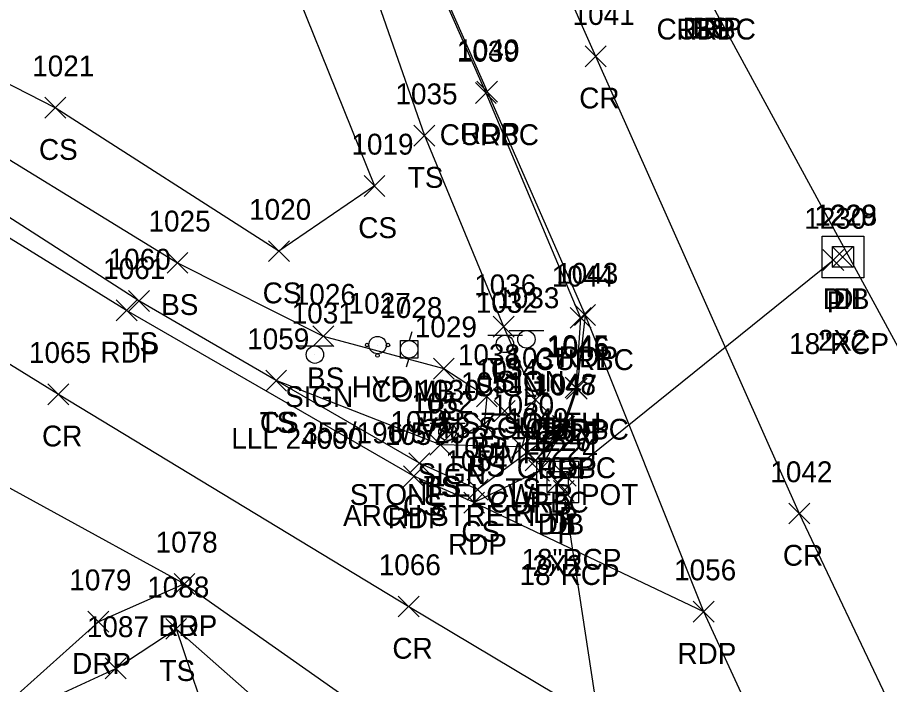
# Model space of a CAD drawing. Extents: x 1504228 to 1506103, y 437717 to 440106.
# Drawn here: x 1505043.8 to 1505127.3, y 438378 to 438441.9 of the extents above; entities that cross this region are included whole.
import ezdxf

# ---------------------------------------------------------------- set-up
doc = ezdxf.new("R2010")
doc.units = 0
for name, color, linetype in [('D_A', 7, 'Continuous'), ('D_C', 7, 'Continuous'), ('D_I', 7, 'Continuous'), ('D_TIC', 7, 'Continuous'), ('DCP', 7, 'Continuous'), ('DS', 7, 'Continuous'), ('L_A', 7, 'Continuous'), ('L_C', 7, 'Continuous'), ('L_I', 7, 'Continuous'), ('L_TIC', 7, 'Continuous'), ('LELB', 7, 'Continuous'), ('P_A', 7, 'Continuous'), ('P_I', 7, 'Continuous'), ('P_TIC', 7, 'Continuous'), ('PET', 7, 'Continuous'), ('PRC', 7, 'Continuous'), ('R_A', 7, 'Continuous'), ('R_I', 7, 'Continuous'), ('R_TIC', 7, 'Continuous'), ('RC', 7, 'Continuous'), ('RDP', 7, 'Continuous'), ('S_A', 7, 'Continuous'), ('S_C', 7, 'Continuous'), ('S_I', 7, 'Continuous'), ('SSGN', 7, 'Continuous'), ('U_A', 7, 'Continuous'), ('U_C', 7, 'Continuous'), ('U_I', 7, 'Continuous'), ('UP', 7, 'Continuous'), ('UWFH', 7, 'Continuous')]:
    doc.layers.add(name, color=color, linetype=linetype)

msp = doc.modelspace()

# ---------------------------------------------------------------- linework, layer by layer
at = {"layer": 'D_TIC'}
for points in [[(1505120.954, 438417.648), (1505122.954, 438419.648)], [(1505122.954, 438417.648), (1505120.954, 438419.648)], [(1505121.856, 438417.952), (1505123.856, 438419.952)], [(1505123.856, 438417.952), (1505121.856, 438419.952)], [(1505094.543, 438396.356), (1505096.543, 438398.356)], [(1505096.543, 438396.356), (1505094.543, 438398.356)], [(1505095.319, 438396.985), (1505097.319, 438398.985)], [(1505097.319, 438396.985), (1505095.319, 438398.985)], [(1505095.144, 438395.524), (1505097.144, 438397.524)], [(1505097.144, 438395.524), (1505095.144, 438397.524)]]:
    msp.add_lwpolyline(points, dxfattribs=at)
at = {"layer": 'DCP'}
for points in [[(1505096.319, 438397.985), (1505121.954, 438418.648)], [(1505105.611, 438334.574), (1505096.144, 438396.524)]]:
    msp.add_lwpolyline(points, dxfattribs=at)
at = {"layer": 'DS'}
for p, q in [((1505120.896, 438420.956), (1505124.896, 438420.956)), ((1505120.896, 438416.956), (1505120.896, 438420.956)), ((1505124.896, 438420.956), (1505124.896, 438416.956)), ((1505121.896, 438417.956), (1505121.896, 438419.956)), ((1505121.896, 438419.956), (1505123.896, 438419.956)), ((1505123.896, 438419.956), (1505123.896, 438417.956)), ((1505122.901, 438418.958), (1505122.901, 438418.958)), ((1505122.901, 438418.958), (1505122.901, 438418.958)), ((1505123.896, 438417.956), (1505121.896, 438417.956)), ((1505124.896, 438416.956), (1505120.896, 438416.956)), ((1505093.564, 438399.391), (1505097.564, 438399.391)), ((1505093.564, 438395.391), (1505093.564, 438399.391)), ((1505097.564, 438399.391), (1505097.564, 438395.391)), ((1505094.564, 438396.391), (1505094.564, 438398.391)), ((1505094.564, 438398.391), (1505096.564, 438398.391)), ((1505096.564, 438398.391), (1505096.564, 438396.391)), ((1505095.569, 438397.393), (1505095.569, 438397.393)), ((1505095.569, 438397.393), (1505095.569, 438397.393)), ((1505096.564, 438396.391), (1505094.564, 438396.391)), ((1505097.564, 438395.391), (1505093.564, 438395.391))]:
    msp.add_line(p, q, dxfattribs=at)
at = {"layer": 'L_TIC'}
for points in [[(1505046.428, 438432.247), (1505048.428, 438434.247)], [(1505048.428, 438432.247), (1505046.428, 438434.247)], [(1505081.791, 438429.573), (1505083.791, 438431.573)], [(1505083.791, 438429.573), (1505081.791, 438431.573)], [(1505077.011, 438424.753), (1505079.011, 438426.753)], [(1505079.011, 438424.753), (1505077.011, 438426.753)], [(1505067.86, 438418.506), (1505069.86, 438420.506)], [(1505069.86, 438418.506), (1505067.86, 438420.506)], [(1505058.135, 438417.385), (1505060.135, 438419.385)], [(1505060.135, 438417.385), (1505058.135, 438419.385)], [(1505054.447, 438413.732), (1505056.447, 438415.732)], [(1505056.447, 438413.732), (1505054.447, 438415.732)], [(1505089.382, 438411.272), (1505091.382, 438413.272)], [(1505091.382, 438411.272), (1505089.382, 438413.272)], [(1505072.108, 438410.364), (1505074.108, 438412.364)], [(1505074.108, 438410.364), (1505072.108, 438412.364)], [(1505083.652, 438407.249), (1505085.652, 438409.249)], [(1505085.652, 438407.249), (1505083.652, 438409.249)], [(1505067.594, 438406.103), (1505069.594, 438408.103)], [(1505069.594, 438406.103), (1505067.594, 438408.103)], [(1505067.594, 438406.103), (1505069.594, 438408.103)], [(1505069.594, 438406.103), (1505067.594, 438408.103)], [(1505087.769, 438404.579), (1505089.769, 438406.579)], [(1505089.769, 438404.579), (1505087.769, 438406.579)], [(1505092.426, 438404.26), (1505094.426, 438406.26)], [(1505094.426, 438404.26), (1505092.426, 438406.26)], [(1505089.481, 438403.182), (1505091.481, 438405.182)], [(1505091.481, 438403.182), (1505089.481, 438405.182)], [(1505087.501, 438401.901), (1505089.501, 438403.901)], [(1505089.501, 438401.901), (1505087.501, 438403.901)], [(1505095.052, 438401.754), (1505097.052, 438403.754)], [(1505097.052, 438401.754), (1505095.052, 438403.754)], [(1505083.317, 438399.963), (1505085.317, 438401.963)], [(1505085.317, 438399.963), (1505083.317, 438401.963)], [(1505083.317, 438399.963), (1505085.317, 438401.963)], [(1505085.317, 438399.963), (1505083.317, 438401.963)], [(1505091.124, 438399.75), (1505093.124, 438401.75)], [(1505093.124, 438399.75), (1505091.124, 438401.75)], [(1505081.309, 438398.178), (1505083.309, 438400.178)], [(1505083.309, 438398.178), (1505081.309, 438400.178)], [(1505086.891, 438395.657), (1505088.891, 438397.657)], [(1505088.891, 438395.657), (1505086.891, 438397.657)], [(1505058.009, 438382.324), (1505060.009, 438384.324)], [(1505060.009, 438382.324), (1505058.009, 438384.324)], [(1505058.009, 438382.324), (1505060.009, 438384.324)], [(1505060.009, 438382.324), (1505058.009, 438384.324)], [(1505052.227, 438378.528), (1505054.227, 438380.528)], [(1505054.227, 438378.528), (1505052.227, 438380.528)]]:
    msp.add_lwpolyline(points, dxfattribs=at)
at = {"layer": 'LELB'}
for points in [[(1505066.129, 438478.342), (1505082.791, 438430.573), (1505090.382, 438412.272), (1505093.426, 438405.26), (1505092.124, 438400.75), (1505084.317, 438400.963), (1505068.594, 438407.103), (1505055.447, 438414.732), (1505017.226, 438439.337)], [(1505057.76, 438475.633), (1505067.049, 438452.95), (1505078.011, 438425.753), (1505068.86, 438419.506), (1505047.428, 438433.247), (1505026.834, 438443.799), (1505009.486, 438446.928)], [(1505009.486, 438446.928), (1505034.88, 438433.257), (1505059.135, 438418.385), (1505073.108, 438411.364), (1505084.652, 438408.249), (1505088.769, 438405.579), (1505088.501, 438402.901), (1505084.317, 438400.963)], [(1505096.052, 438402.754), (1505087.891, 438396.657), (1505082.309, 438399.178), (1505068.594, 438407.103)], [(1505039.492, 438373.185), (1505053.227, 438379.528), (1505059.009, 438383.324), (1505062.619, 438372.642), (1505066.294, 438362.487)], [(1505059.009, 438383.324), (1505071.79, 438372.048), (1505087.996, 438363.895), (1505093.24, 438355.147)]]:
    msp.add_lwpolyline(points, dxfattribs=at)
at = {"layer": 'P_TIC'}
for points in [[(1505098.188, 438437.177), (1505100.188, 438439.177)], [(1505100.188, 438437.177), (1505098.188, 438439.177)], [(1505087.799, 438433.786), (1505089.799, 438435.786)], [(1505089.799, 438433.786), (1505087.799, 438435.786)], [(1505053.269, 438412.829), (1505055.269, 438414.829)], [(1505055.269, 438412.829), (1505053.269, 438414.829)], [(1505097.18, 438412.38), (1505099.18, 438414.38)], [(1505099.18, 438412.38), (1505097.18, 438414.38)], [(1505097.18, 438412.38), (1505099.18, 438414.38)], [(1505099.18, 438412.38), (1505097.18, 438414.38)], [(1505046.73, 438404.795), (1505048.73, 438406.795)], [(1505048.73, 438404.795), (1505046.73, 438406.795)], [(1505096.396, 438405.327), (1505098.396, 438407.327)], [(1505098.396, 438405.327), (1505096.396, 438407.327)], [(1505095.167, 438401.681), (1505097.167, 438403.681)], [(1505097.167, 438401.681), (1505095.167, 438403.681)], [(1505092.782, 438397.474), (1505094.782, 438399.474)], [(1505094.782, 438397.474), (1505092.782, 438399.474)], [(1505080.778, 438396.942), (1505082.778, 438398.942)], [(1505082.778, 438396.942), (1505080.778, 438398.942)], [(1505086.561, 438394.414), (1505088.561, 438396.414)], [(1505088.561, 438394.414), (1505086.561, 438396.414)], [(1505086.561, 438394.414), (1505088.561, 438396.414)], [(1505088.561, 438394.414), (1505086.561, 438396.414)], [(1505117.696, 438393.368), (1505119.696, 438395.368)], [(1505119.696, 438393.368), (1505117.696, 438395.368)], [(1505058.812, 438386.625), (1505060.812, 438388.625)], [(1505060.812, 438386.625), (1505058.812, 438388.625)], [(1505080.29, 438384.458), (1505082.29, 438386.458)], [(1505082.29, 438384.458), (1505080.29, 438386.458)], [(1505108.535, 438383.969), (1505110.535, 438385.969)], [(1505110.535, 438383.969), (1505108.535, 438385.969)], [(1505108.535, 438383.969), (1505110.535, 438385.969)], [(1505110.535, 438383.969), (1505108.535, 438385.969)]]:
    msp.add_lwpolyline(points, dxfattribs=at)
at = {"layer": 'PET'}
for points in [[(1505068.915, 438479.856), (1505088.799, 438434.786), (1505098.18, 438413.38), (1505109.535, 438384.969), (1505120.749, 438360.591), (1505130.106, 438339.585), (1505143.01, 438310.872), (1505160.435, 438272.099), (1505181.323, 438230.832), (1505199.453, 438238.762), (1505211.655, 438244.29), (1505203.781, 438257.456), (1505193.868, 438276.083), (1505183.087, 438301.098), (1505168.267, 438328.998), (1505148.647, 438369.04), (1505141.294, 438386.172), (1505109.448, 438444.779), (1505106.082, 438450.67), (1505101.61, 438460.04), (1505094.486, 438475.336), (1505087.609, 438490.541)], [(1505098.18, 438413.38), (1505097.396, 438406.327), (1505096.167, 438402.681), (1505093.782, 438398.474), (1505087.561, 438395.414), (1505081.778, 438397.942), (1505054.269, 438413.829), (1505015.974, 438437.476)], [(1505001.775, 438421.501), (1505032.758, 438402.461), (1505059.812, 438387.625), (1505089.41, 438366.798), (1505108.599, 438355.578), (1505130.106, 438339.585)], [(1505087.561, 438395.414), (1505109.535, 438384.969)]]:
    msp.add_lwpolyline(points, dxfattribs=at)
at = {"layer": 'PRC'}
for points in [[(1505079.068, 438483.546), (1505099.188, 438438.177), (1505118.696, 438394.368), (1505142.43, 438344.291), (1505155.616, 438317.19), (1505174.858, 438280.77), (1505189.016, 438255.493), (1505199.453, 438238.762)], [(1505010.682, 438428.714), (1505047.73, 438405.795), (1505081.29, 438385.458), (1505105.541, 438371.01), (1505120.749, 438360.591)]]:
    msp.add_lwpolyline(points, dxfattribs=at)
at = {"layer": 'R_TIC'}
for points in [[(1505087.674, 438433.658), (1505089.674, 438435.658)], [(1505089.674, 438433.658), (1505087.674, 438435.658)], [(1505096.758, 438412.113), (1505098.758, 438414.113)], [(1505098.758, 438412.113), (1505096.758, 438414.113)], [(1505096.284, 438405.444), (1505098.284, 438407.444)], [(1505098.284, 438405.444), (1505096.284, 438407.444)], [(1505095.052, 438401.754), (1505097.052, 438403.754)], [(1505097.052, 438401.754), (1505095.052, 438403.754)], [(1505092.436, 438398.459), (1505094.436, 438400.459)], [(1505094.436, 438398.459), (1505092.436, 438400.459)], [(1505058.812, 438386.625), (1505060.812, 438388.625)], [(1505060.812, 438386.625), (1505058.812, 438388.625)], [(1505050.559, 438383.007), (1505052.559, 438385.007)], [(1505052.559, 438383.007), (1505050.559, 438385.007)]]:
    msp.add_lwpolyline(points, dxfattribs=at)
at = {"layer": 'RC'}
msp.add_lwpolyline([(1505068.747, 438479.791), (1505088.674, 438434.658), (1505097.758, 438413.113), (1505097.284, 438406.444), (1505096.052, 438402.754), (1505093.436, 438399.459)], dxfattribs=at)
at = {"layer": 'RDP'}
msp.add_lwpolyline([(1505059.812, 438387.625), (1505051.559, 438384.007), (1505039.492, 438373.185), (1505022.739, 438357.365)], dxfattribs=at)
at = {"layer": 'SSGN'}
for p, q in [((1505090.911, 438411.891), (1505094.244, 438411.891)), ((1505088.853, 438411.451), (1505092.186, 438411.451)), ((1505092.558, 438411.057), (1505092.558, 438411.057)), ((1505070.654, 438410.423), (1505073.988, 438410.423)), ((1505090.5, 438410.617), (1505090.5, 438410.617)), ((1505072.301, 438409.59), (1505072.301, 438409.59)), ((1505083.353, 438403.035), (1505086.686, 438403.035)), ((1505085, 438402.202), (1505085, 438402.202))]:
    msp.add_line(p, q, dxfattribs=at)
for centre in [(1505092.558, 438411.057), (1505090.5, 438410.617), (1505072.301, 438409.59), (1505085, 438402.202)]:
    msp.add_circle(centre, 0.833, dxfattribs=at)
at = {"layer": 'UP'}
for p, q in [((1505081.582, 438411.767), (1505081.332, 438410.934)), ((1505080.499, 438409.267), (1505080.499, 438410.934)), ((1505080.499, 438410.934), (1505082.166, 438410.934)), ((1505082.166, 438410.934), (1505082.166, 438409.267)), ((1505081.332, 438410.101), (1505081.332, 438410.101)), ((1505082.166, 438409.267), (1505080.499, 438409.267)), ((1505081.082, 438408.434), (1505081.332, 438409.267))]:
    msp.add_line(p, q, dxfattribs=at)
msp.add_circle((1505081.332, 438410.101), 0.833, dxfattribs=at)
at = {"layer": 'UWFH'}
msp.add_line((1505078.3, 438410.507), (1505078.3, 438410.507), dxfattribs=at)
for centre, radius in [((1505078.3, 438410.507), 0.833), ((1505077.3, 438410.507), 0.167), ((1505079.3, 438410.507), 0.167), ((1505078.3, 438409.507), 0.167)]:
    msp.add_circle(centre, radius, dxfattribs=at)

# ---------------------------------------------------------------- texts
at = {"layer": 'D_A'}
for s, p in [('DIB', (1505120.959, 438413.952)), ('DI', (1505121.956, 438413.958)), ('P', (1505121.332, 438413.648)), ('P', (1505095.697, 438392.985)), ('DIB', (1505093.645, 438392.356)), ('DI', (1505094.624, 438392.393)), ('P', (1505095.522, 438391.524))]:
    msp.add_text(s, height=2, dxfattribs=at).set_placement(p)
at = {"layer": 'D_C'}
for s, p in [('2X2', (1505120.476, 438409.958)), ('18"RCP', (1505117.725, 438409.648)), ('18"RCP', (1505092.091, 438388.985)), ('2X2', (1505093.144, 438388.393)), ('18"RCP', (1505091.915, 438387.524))]:
    msp.add_text(s, height=2, dxfattribs=at).set_placement(p)
at = {"layer": 'D_I'}
for s, p in [('1230', (1505119.174, 438421.648)), ('1229', (1505120.155, 438421.952)), ('1228', (1505120.208, 438421.958)), ('1225', (1505093.626, 438400.985)), ('1226', (1505092.795, 438400.356)), ('1227', (1505092.876, 438400.393)), ('1224', (1505093.451, 438399.524))]:
    msp.add_text(s, height=2, dxfattribs=at).set_placement(p)
at = {"layer": 'L_A'}
for s, p in [('BS', (1505108.494, 438439.862)), ('CS', (1505045.869, 438428.247)), ('TS', (1505081.201, 438425.573)), ('CS', (1505076.452, 438420.753)), ('CS', (1505067.301, 438414.506)), ('BS', (1505057.576, 438413.385)), ('TS', (1505053.856, 438409.732)), ('TS', (1505088.792, 438407.272)), ('BS', (1505071.549, 438406.364)), ('BS', (1505083.092, 438403.249)), ('TS', (1505067.004, 438402.103)), ('CS', (1505067.035, 438402.103)), ('BS', (1505087.21, 438400.579)), ('TS', (1505091.835, 438400.26)), ('MMF', (1505087.765, 438399.182)), ('BS', (1505086.942, 438397.901)), ('CS', (1505094.493, 438397.754)), ('TS', (1505082.726, 438395.963)), ('BS', (1505082.758, 438395.963)), ('TS', (1505090.533, 438395.75)), ('CS', (1505080.75, 438394.178)), ('CS', (1505086.332, 438391.657)), ('TS', (1505057.419, 438378.324)), ('TS', (1505057.419, 438378.324))]:
    msp.add_text(s, height=2, dxfattribs=at).set_placement(p)
at = {"layer": 'L_C'}
msp.add_text('STONE FLOWER POT', height=2, dxfattribs=at).set_placement((1505075.639, 438395.182))
at = {"layer": 'L_I'}
for s, p in [('1021', (1505045.223, 438436.247)), ('1035', (1505080.02, 438433.573)), ('1019', (1505075.799, 438428.753)), ('1020', (1505066.002, 438422.506)), ('1025', (1505056.363, 438421.385)), ('1060', (1505052.541, 438417.732)), ('1036', (1505087.556, 438415.272)), ('1026', (1505070.281, 438414.364)), ('1029', (1505081.872, 438411.249)), ('1059', (1505065.815, 438410.103)), ('1059', (1505065.815, 438410.103)), ('1038', (1505085.997, 438408.579)), ('1037', (1505090.654, 438408.26)), ('1034', (1505087.71, 438407.182)), ('1051', (1505086.296, 438405.901)), ('1048', (1505093.28, 438405.754)), ('1052', (1505081.545, 438403.963)), ('1052', (1505081.545, 438403.963)), ('1050', (1505089.266, 438403.75)), ('1058', (1505079.538, 438402.178)), ('1055', (1505085.119, 438399.657)), ('1088', (1505056.237, 438386.324)), ('1088', (1505056.237, 438386.324)), ('1087', (1505050.456, 438382.528))]:
    msp.add_text(s, height=2, dxfattribs=at).set_placement(p)
at = {"layer": 'P_A'}
for s, p in [('RDP', (1505106.936, 438439.779)), ('CR', (1505097.621, 438433.177)), ('RDP', (1505086.287, 438429.786)), ('RDP', (1505051.757, 438408.829)), ('RDP', (1505095.668, 438408.38)), ('RDP', (1505095.668, 438408.38)), ('CR', (1505046.163, 438400.795)), ('RDP', (1505094.884, 438401.327)), ('RDP', (1505093.655, 438397.681)), ('RDP', (1505091.27, 438393.474)), ('RDP', (1505079.266, 438392.942)), ('RDP', (1505085.049, 438390.414)), ('RDP', (1505085.049, 438390.414)), ('CR', (1505117.129, 438389.368)), ('RDP', (1505057.301, 438382.625)), ('CR', (1505079.723, 438380.458)), ('RDP', (1505107.023, 438379.969)), ('RDP', (1505107.023, 438379.969))]:
    msp.add_text(s, height=2, dxfattribs=at).set_placement(p)
at = {"layer": 'P_I'}
for s, p in [('1041', (1505096.984, 438441.177)), ('1040', (1505085.941, 438437.786)), ('1061', (1505052.017, 438416.829)), ('1043', (1505095.408, 438416.38)), ('1043', (1505095.408, 438416.38)), ('1046', (1505094.569, 438409.327)), ('1065', (1505044.911, 438408.795)), ('1047', (1505093.395, 438405.681)), ('1053', (1505091.01, 438401.474)), ('1057', (1505079.006, 438400.942)), ('1054', (1505084.79, 438398.414)), ('1054', (1505084.79, 438398.414)), ('1042', (1505115.925, 438397.368)), ('1078', (1505057.041, 438390.625)), ('1066', (1505078.416, 438388.458)), ('1056', (1505106.708, 438387.969)), ('1056', (1505106.708, 438387.969))]:
    msp.add_text(s, height=2, dxfattribs=at).set_placement(p)
at = {"layer": 'R_A'}
for s, p in [('CURBC', (1505105.03, 438439.779)), ('DRP', (1505107.541, 438439.862)), ('CURBC', (1505084.257, 438429.658)), ('CURBC', (1505093.341, 438408.113)), ('CURBC', (1505092.866, 438401.444)), ('CURBC', (1505091.635, 438397.754)), ('CURBC', (1505089.019, 438394.459)), ('DRP', (1505057.301, 438382.625)), ('DRP', (1505049.047, 438379.007))]:
    msp.add_text(s, height=2, dxfattribs=at).set_placement(p)
at = {"layer": 'R_I'}
for s, p in [('1039', (1505085.895, 438437.658)), ('1044', (1505094.987, 438416.113)), ('1045', (1505094.512, 438409.444)), ('1048', (1505093.28, 438405.754)), ('1049', (1505090.657, 438402.459)), ('1078', (1505057.041, 438390.625)), ('1079', (1505048.779, 438387.007))]:
    msp.add_text(s, height=2, dxfattribs=at).set_placement(p)
at = {"layer": 'S_A'}
for p in [(1505087.637, 438405.597), (1505089.695, 438406.037), (1505069.439, 438404.57), (1505082.137, 438397.182)]:
    msp.add_text('SIGN', height=2, dxfattribs=at).set_placement(p)
at = {"layer": 'S_C'}
for s, p in [('VT3 SOUTH', (1505082.307, 438401.597)), ('US7 SOUTH', (1505084.412, 438402.037)), ('LLL 24000', (1505064.289, 438400.57)), ('ARCH STREET', (1505075.004, 438393.182))]:
    msp.add_text(s, height=2, dxfattribs=at).set_placement(p)
at = {"layer": 'S_I'}
for s, p in [('1033', (1505089.766, 438414.037)), ('1032', (1505087.708, 438413.597)), ('1031', (1505070.077, 438412.57)), ('1030', (1505082.122, 438405.182))]:
    msp.add_text(s, height=2, dxfattribs=at).set_placement(p)
at = {"layer": 'U_A'}
for s, p in [('HYD', (1505075.82, 438405.507)), ('COMB', (1505077.718, 438405.101))]:
    msp.add_text(s, height=2, dxfattribs=at).set_placement(p)
at = {"layer": 'U_C'}
msp.add_text('355/196/5/20', height=2, dxfattribs=at).set_placement((1505071.088, 438401.101))
at = {"layer": 'U_I'}
for s, p in [('1027', (1505075.528, 438413.507)), ('1028', (1505078.561, 438413.101))]:
    msp.add_text(s, height=2, dxfattribs=at).set_placement(p)

doc.saveas('drawing.dxf')
